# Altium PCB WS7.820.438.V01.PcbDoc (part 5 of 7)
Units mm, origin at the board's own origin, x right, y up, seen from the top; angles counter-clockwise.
Board outline 143.01 x 224 mm, 4 copper layers (Top Layer, G2, S3, Bottom Layer); 863 components, 638 nets, 2623 pads, 4664 vias.
Unrouted connection lines stored in the file: 16.
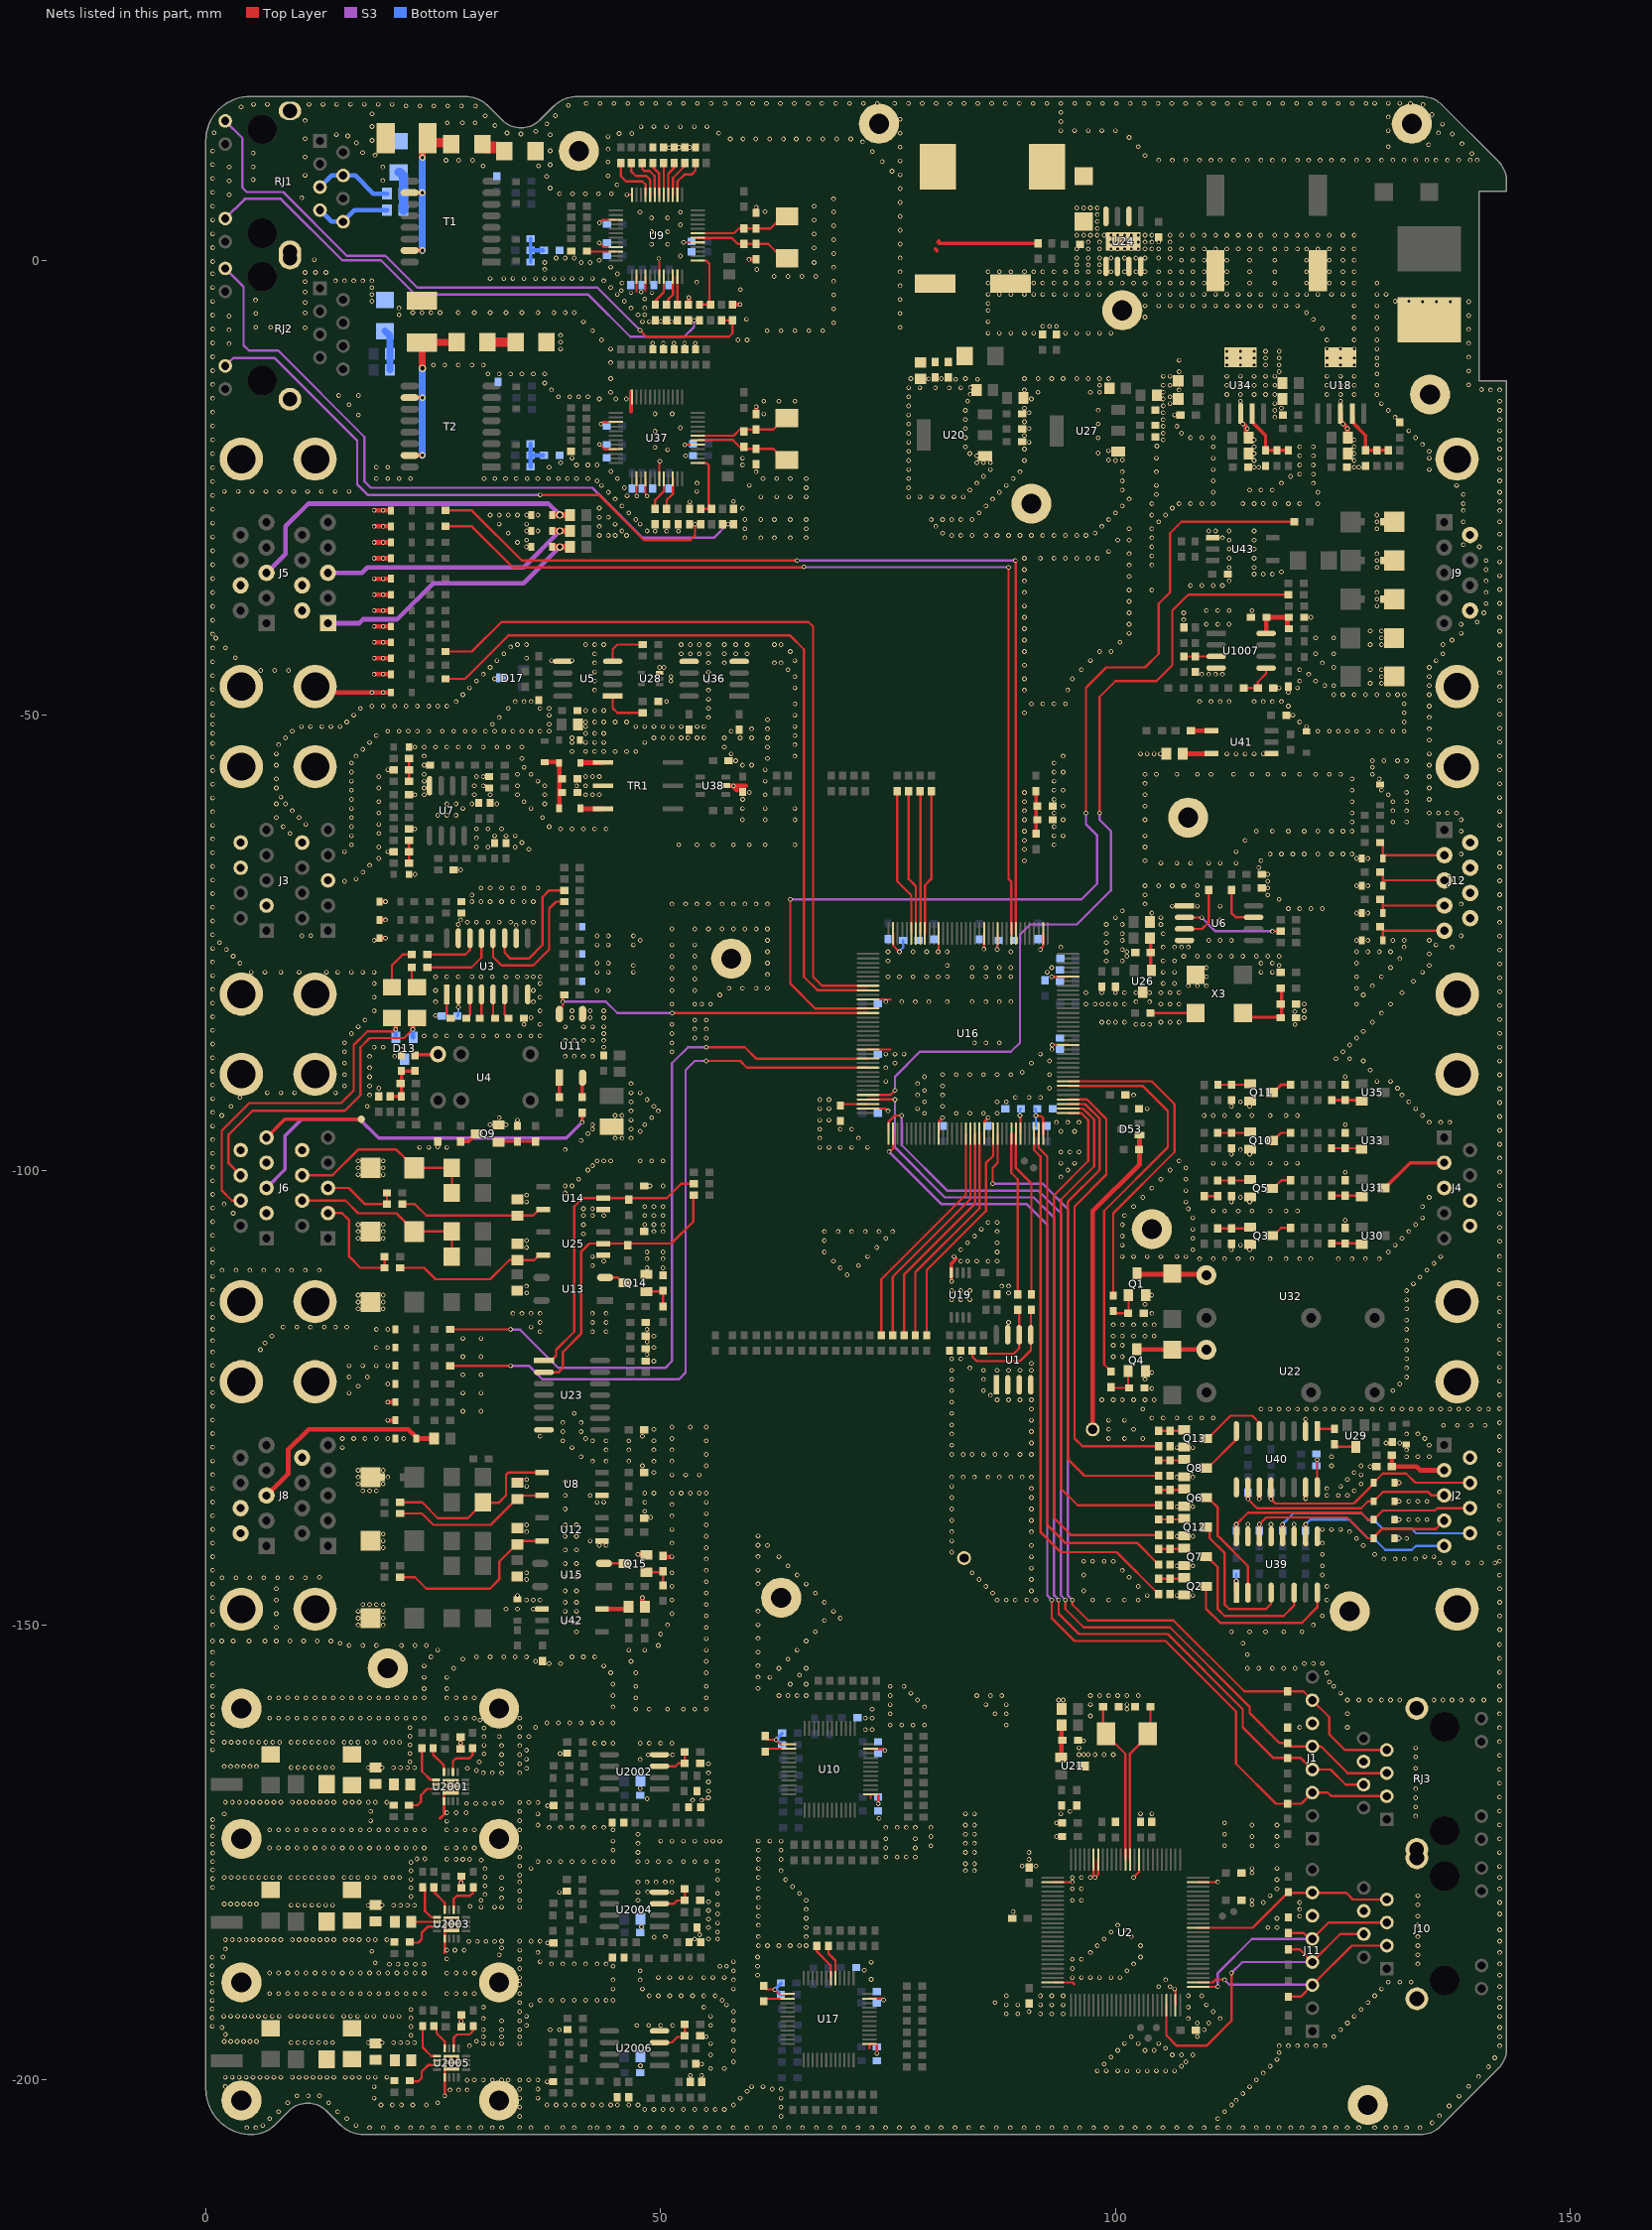
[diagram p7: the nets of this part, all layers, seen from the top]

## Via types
v1: diameter 0.508, hole 0.305, Top Layer to Bottom Layer, tented both sides, 4404 vias
v2: diameter 0.508, hole 0.3, Top Layer to Bottom Layer, tented both sides, 200 vias
v3: diameter 0.813, hole 0.508, Top Layer to Bottom Layer, tented both sides, 31 vias
v4: diameter 0.457, hole 0.305, Top Layer to Bottom Layer, tented both sides, 10 vias
v5: diameter 0.66, hole 0.406, Top Layer to Bottom Layer, tented both sides, 9 vias
v6: diameter 0.762, hole 0.406, Top Layer to Bottom Layer, tented both sides, 6 vias
v7: diameter 0.711, hole 0.406, Top Layer to Bottom Layer, tented both sides, 4 vias

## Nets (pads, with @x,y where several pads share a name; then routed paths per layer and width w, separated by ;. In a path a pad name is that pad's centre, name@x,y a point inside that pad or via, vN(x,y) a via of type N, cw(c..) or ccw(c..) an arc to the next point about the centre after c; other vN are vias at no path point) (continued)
GND: (continued)
  other v1: 128.5,17.25 130,17.25 131.25,17.25
  other v2: 0.75,-151.75 1.75,-151.75 3,-151.75 4.75,-151.75 6.5,-151.75 7.75,-151.75 9.25,-151.75 10.75,-151.75 12.25,-151.75 13.75,-151.75 55,-149 36,-148.25 55,-147.75 55,-146.5 86.5,-146.5 40.75,-146.25 55,-145.25 35.25,-145 40.75,-144.75 55,-144 90.75,-143.75 40.75,-143.25 55,-142.75 40.75,-141.75 55,-141.5 43.25,-141.25 42.25,-140.75 40.75,-140.25 55,-140.25 35.25,-139.75 35.25,-139 40.75,-139 55,-139 90.75,-138.5 55,-137.75 48.25,-137.5 82,-137.25 48.26,-136.525 43,-136.5 43.75,-136.5 55,-136.5 90.75,-136 42.25,-135.75 48.25,-135.5 55,-135.5 35.25,-134.75 82,-134.75 19.5,-134.5 35.25,-134 20,-133.75 87.25,-133.75 89.75,-133.75 48,-132.5 86.75,-131.25 89.5,-131.25 15,-130.5 49.25,-129.75 15,-129.5 16.25,-129.5 17.5,-129.5 18.75,-129.5 20,-129.5 48,-129.25 39.25,-128.75 49.25,-128.5 53.25,-128.25 82,-125.5 15.75,-124.5 16.75,-123.75 20,-123.5 82,-123 17.75,-122.75 15.75,-121.5 17.25,-121.5 18.75,-121.5 20,-121.5 48.5,-120.25 6,-119.75 20,-119.5 6.5,-119 48.514,-118.872 7.25,-118.25 20,-117.5 48.5,-117.5 8.5,-117.25 10,-117.25 11.5,-117.25 13,-117.25 14.25,-117.25 15.5,-117.25 35.25,-113.5 43.75,-110 42.5,-109.5 35.25,-107.75 48.25,-106 49.25,-106 43.75,-105 48.25,-105 49.25,-105 3,-104.75 42.5,-104.25 48.25,-104 49.25,-104 2,-103.75 35.25,-102.75 48.823,-101.75 43,-99 43.75,-99 44.5,-99 42,-96 42.5,-95 1.75,-94 2.75,-93 3.75,-92 41.5,-87.5 42.5,-87.5 43.75,-86.5 42.5,-85.75 43.75,-85 35.75,-83.25 42.25,-83.25 75,-76 77.75,-76 79.25,-76 10.55,-74.25 11.55,-74.217 59,-61.5 59.007,-59.25 59.757,-58.5 58.257,-55 19.5,-40.25 35.25,-30.75 35.25,-29.75 35.25,-29 35.25,-28 19.5,-27.5 43,-24.25 20,-22.75 37.25,-12.5 18.25,-4.5 18.25,-3.75 33.75,-2 35,-2 36.25,-2 37.25,-2 38.25,-2 45.25,-1.5 41.25,-0.25 42.25,-0.25 38.5,0.25
  other v4: 49.116,-9.111 50.29,-9.111 51.465,-9.111 52.64,-9.111 53.815,-9.111 51.228,-6.731 50.015,-6.706 46.736,-3.556 49.022,-3.556 49.809,0.178
GND2: C19.1 C20.1 C108.1 C110.1 C111.1 D17.3 D18.2 J3.B9 J3.B11 R33.2 R304.1 TR1.5 U5.5 U28.3 U36.5
  other v1: 15.25,-65 16,-64.25 16,-63.25 9.25,-63 8.5,-62.25 16,-62.25 11,-62 7.75,-61.25 10.25,-61.25 16,-61.25 9.5,-60.5 16,-60.25 7.75,-59.75 8.75,-59.75 16,-59.25 8.25,-59 16,-58.25 7.75,-58 16,-57.25 7.75,-57 16,-56.25 7.75,-55.5 16,-55.25 16.5,-54.5 7.75,-54.25 40.25,-54 41.75,-54 42.75,-54 43.75,-54 45,-54 46.25,-54 47.25,-54 17.25,-53.75 8,-53.25 18,-53 40.25,-53 41.75,-53 42.75,-53 43.75,-53 48.25,-53 8.75,-52.5 40.25,-52.5 49.25,-52.5 50.25,-52.5 51.25,-52.5 52.25,-52.5 53,-52.5 54,-52.5 54.75,-52.5 18.75,-52.25 41.75,-52 42.75,-52 43.75,-52 9.5,-51.75 20,-51.75 21.25,-51.75 22.25,-51.75 23.25,-51.75 24.5,-51.75 26,-51.75 27.25,-51.75 28.5,-51.75 29.5,-51.75 30.75,-51.75 31.75,-51.75 32.75,-51.75 33.75,-51.75 34.75,-51.75 35.75,-51.75 36.75,-51.75 37.75,-51.75 10.5,-51.25 11.5,-51.25 12.75,-51.25 13.75,-51.25 14.75,-51.25 41.75,-51.25 47.25,-51.25 48.25,-51.25 49.25,-51.25 50.25,-51.25 51.25,-51.25 52.25,-51.25 54,-51.25 54.75,-51.25 31.5,-51 37.75,-51 15.5,-50.75 41.75,-50.75 42.75,-50.75 43.75,-50.75 45,-50.75 46.25,-50.75 32.25,-50.25 55.25,-50.25 16.25,-50 37.75,-50 41.75,-49.5 42.75,-49.5 43.75,-49.5 17,-49.25 33.25,-49.25 36.75,-49.25 37.75,-49.25 55.25,-49.25 18.25,-49 19.5,-49 20.75,-49 22,-49 23.25,-49 24.5,-49 25.5,-49 26.5,-49 27.5,-48.5 34,-48.5 35,-48.5 35.75,-48.5 55.25,-48.25 28.25,-47.75 42.75,-47.25 55.25,-47.25 29,-47 29.75,-46.25 42.75,-46.25 55.25,-46.25 31.75,-46 30.5,-45.5 42.75,-45.25 55.25,-45.25 31.25,-44.75 42.75,-44.25 55.25,-44.25 32,-44 38,-44 40.25,-44 35.25,-43.75 32.75,-43.25 42.75,-43.25 52.25,-43.25 55.25,-43.25 33.5,-42.5 34.25,-42.25 35.25,-42.25 41.75,-42.25 42.75,-42.25 43.75,-42.25 52.25,-42.25 53.25,-42.25 54.25,-42.25 55.25,-42.25
  other v2: 41.757,-58.75 42.507,-58.75 43.257,-58.75 40.757,-57.75 41.757,-57.75 41.757,-56.75 42.507,-56.75 43.257,-56.75 50.632,-48.5 51.132,-46.25 51.132,-45.75 49.882,-44.75 50.382,-44.75 53.25,-43.25 54.25,-43.25
green_24V: J4.2 U31.3 | length 7.8
  Top Layer w0.381: U31.3@129.47,-101.96 129.62,-101.96 132.387,-99.193 J4.2@136.139,-99.193
green_ctrl: R106.2 R261.1 | length 1.5
  Top Layer w0.254: R106.2@109.75,-102.85 R261.1@111.25,-102.85
I_SENSOR1: D71.1 J12.5 R107.2 | length 8.4
  Top Layer w0.254: R107.2@129.1,-73.25 129.127,-73.25 129.4,-73.523 129.4,-73.697 ; D71.1@129.4,-74.75 129.4,-73.697 ; J12.5@136.16,-73.697 129.4,-73.697
I_SENSOR2: D72.1 J12.4 R174.2 | length 8.4
  Top Layer w0.254: R174.2@129.1,-70.25 129.127,-70.25 129.4,-70.523 129.4,-70.927 ; D72.1@129.4,-71.75 129.4,-70.927 ; J12.4@136.16,-70.927 129.4,-70.927
I_SENSOR3: D73.1 J12.3 R175.2 | length 8.4
  Top Layer w0.254: R175.2@129.1,-67.25 129.127,-67.25 129.4,-67.523 129.4,-68.157 ; D73.1@129.4,-68.75 129.4,-68.157 ; J12.3@136.16,-68.157 129.4,-68.157
IO_reset: R38.2 R152.2 U40.16 | length 3.7
  Top Layer w0.254: U40.16@122.174,-134.874 v1(122.174,-131.826)
  Bottom Layer w0.254: R38.2@122.174,-132.5 v1(122.174,-131.826)
IO_SHIDU: FB7.1 J6.A3 | length 42.6
  Top Layer w0.381: v1(41.362,-94.75) FB7.1@41.362,-93.687
  S3 w0.381: J6.A3@6.666,-101.963 8.706,-99.923 8.706,-96.235 10.529,-94.412 16.912,-94.412 19,-96.5 39.612,-96.5 v1(41.362,-94.75)
IOC_SHIDU: R18.2 U11.6 U16.86 | length 36.4
  Top Layer w0.254: U11.6@38.875,-82.852 38.875,-82.305 39.25,-81.93 v1(39.25,-81.5) 39.25,-80.9 R18.2@39.4,-80.75 ; v1@51.25,-82.75 v1(51.263,-82.737) U16.86@72.801,-82.737
  S3 w0.254: v1(39.25,-81.5) 44,-81.5 45.237,-82.737 v1(51.263,-82.737)
JTCK: J1.5 R8.2 RJ3.5 U16.109 | length 113.8
  Top Layer w0.254: U16.109@75.051,-95.987 75.051,-94.699 75.75,-94 v1(76.5,-94) ; v1(94.498,-147.252) 94.5,-147.254 94.5,-148.25 96.5,-150.25 106,-150.25 114.75,-159 114.75,-159.674 118.059,-162.982 R8.2@118.923,-162.982 118.923,-163.032 119.196,-163.305 119.305,-163.305 119.345,-163.345 J1.5@121.641,-163.345 122.595,-163.345 125.528,-166.278 RJ3.5@129.824,-166.278
  S3 w0.254: v1(76.5,-94) 76.5,-97.25 81.5,-102.25 91.5,-102.25 94,-104.75 94,-146.75 94.498,-147.248 v1(94.498,-147.252)
JTCK-1: J10.5 J11.5 R157.2 U2.76 | length 27.5
  Top Layer w0.254: U2.76@109.096,-189.781 109.112,-189.766 111.234,-189.766 v1(111.25,-189.75) ; R157.2@119,-183.85 120.691,-183.85 121.341,-184.5 J11.5@121.641,-184.5 123.436,-182.705 J10.5@129.84,-182.705
  S3 w0.254: v1(111.25,-189.75) 111.25,-188.25 115,-184.5 J11.5@121.641,-184.5
JTDI: J1.3 R5.1 RJ3.3 U16.110 | length 115.7
  Top Layer w0.254: v1(75.115,-97.967) 75.163,-97.918 75.251,-97.918 75.551,-97.618 U16.110@75.551,-95.987 ; v1(92.998,-147.252) 93,-147.254 93,-149.25 95.5,-151.75 105.5,-151.75 113.25,-159.5 113.25,-165.25 117.65,-169.65 R5.1@118.923,-169.65 120.415,-169.65 J1.3@121.641,-168.425 ; J1.3@121.641,-168.425 123.355,-168.425 123.748,-168.818 RJ3.3@129.824,-168.818
  S3 w0.254: v1(75.115,-97.967) 80.898,-103.75 90.25,-103.75 92.5,-106 92.5,-146.75 92.998,-147.248 v1(92.998,-147.252)
JTDI-1: J10.3 J11.3 R148.1 U2.77 | length 26.1
  Top Layer w0.254: U2.77@109.096,-189.281 110.719,-189.281 111.049,-188.951 111.951,-188.951 v1(112,-189) ; R148.1@119,-190.85 120.371,-190.85 J11.3@121.641,-189.58 125.976,-185.245 J10.3@129.84,-185.245
  S3 w0.254: v1(112,-189) 112.54,-189.54 121.601,-189.54 J11.3@121.641,-189.58
JTDO: J1.7 R7.1 RJ3.7 U16.133 | length 101.1
  Top Layer w0.254: v1(86.5,-101.5) 86.5,-99.75 87.051,-99.199 U16.133@87.051,-95.987 ; v1(95.248,-147.252) 95.25,-147.254 95.25,-147.75 97,-149.5 106.371,-149.5 114.173,-157.302 R7.1@118.923,-157.302 120.677,-157.302 J1.7@121.641,-158.265 123.5,-160.125 123.5,-162 125.238,-163.738 RJ3.7@129.824,-163.738
  S3 w0.254: v1(86.5,-101.5) 92,-101.5 94.75,-104.25 94.75,-146.75 95.248,-147.248 v1(95.248,-147.252)
JTDO-1: J10.7 J11.7 R156.1 U2.89 | length 22.7
  Top Layer w0.254: U2.89@109.096,-183.281 115.069,-183.281 118.677,-179.673 118.727,-179.673 119,-179.4 R156.1@119,-179.35 ; R156.1@119,-179.42 J11.7@121.641,-179.42 125.368,-179.42 126.113,-180.165 J10.7@129.84,-180.165
JTMS: J1.4 R6.1 RJ3.4 U16.105 | length 115.1
  Top Layer w0.254: U16.105@72.801,-92.237 72.807,-92.244 75.744,-92.244 v1(75.75,-92.25) ; v1(93.748,-147.252) 93.75,-147.254 93.75,-148.75 96,-151 105.75,-151 114,-159.25 114,-161.25 117.366,-164.616 R6.1@118.923,-164.616 120.371,-164.616 J1.4@121.641,-165.885 123.635,-165.885 125.298,-167.548 RJ3.4@127.284,-167.548
  S3 w0.254: v1(75.75,-92.25) 75.75,-97.5 81.25,-103 91,-103 93.25,-105.25 93.25,-146.75 93.748,-147.248 v1(93.748,-147.252)
JTMS-1: J10.4 J11.4 R155.1 U2.72 | length 36.9
  Top Layer w0.254: U2.72@105.596,-191.781 105.596,-195.096 106.75,-196.25 110,-196.25 112.75,-193.5 v1(112.75,-188.25) ; R155.1@119,-185.65 120.251,-185.65 J11.4@121.641,-187.04 124.706,-183.975 J10.4@127.3,-183.975
  S3 w0.254: v1(112.75,-188.25) 113.96,-187.04 J11.4@121.641,-187.04
LCD_RX: D13.2 F1.2 J6.A8 | length 35.4
  Top Layer w0.254: J6.A8@3.813,-100.565 2.5,-99.252 2.5,-96.103 5.131,-93.472 15.278,-93.472 17,-91.75 17,-86.5 18,-85.5 21.785,-85.5 v1(22.753,-84.531)
  Top Layer w0.508: v1(22.753,-84.531) 22.753,-83.722 F1.2@23.15,-83.325
  Bottom Layer w0.508: v1(22.753,-84.531) 22.753,-85.373 D13.2@22.794,-85.414
LCD_TX: D13.1 F2.2 J6.A7 | length 38
  Top Layer w0.254: J6.A7@3.826,-103.348 2.859,-103.348 1.75,-102.239 1.75,-95.659 4.775,-92.634 14.866,-92.634 16.25,-91.25 16.25,-86.25 17.75,-84.75 20.578,-84.75 20.796,-84.531 v1(20.853,-84.531)
  Top Layer w0.508: F2.2@20.483,-83.325 20.853,-83.696 v1(20.853,-84.531)
  Bottom Layer w0.508: v1(20.853,-84.531) 20.853,-85.373 D13.1@20.894,-85.414
LINKLED: R78.2 R165.1 U9.25 | length 7.7
  Top Layer w0.254: U9.25@54.092,-0.037 55.003,-0.037 55.365,-0.399 55.365,-3.059 55.365,-3.556 ; R78.2@54.349,-4.756 54.248,-4.858 R165.1@55.442,-4.858 ; 55.365,-3.879 55.365,-3.556 ; R165.1@55.479,-4.895 R165.1@55.442,-4.858 ; 55.365,-3.556 55.365,-4.756 55.467,-4.858 R165.1@55.442,-4.858
LINKLED2: R162.2 R280.2 U37.25 | length 7.2
  Top Layer w0.254: U37.25@54.092,-22.275 55.042,-22.275 55.267,-22.501 R162.2@55.267,-27.311 ; R280.2@54.581,-27.311 R162.2@55.695,-27.311
M_SCL: R2.1 R12.2 U1.6 | length 8.4
  Top Layer w0.254: R2.1@85.5,-119.85 85.5,-119.9 85.773,-120.173 88.827,-120.173 89.425,-119.575 R12.2@89.425,-115.525
M_SDA: R3.1 R11.2 U1.5 | length 12.5
  Top Layer w0.254: R3.1@84.25,-119.85 84.282,-119.882 84.282,-120.532 84.75,-121 89.5,-121 90.695,-119.805 R11.2@90.695,-115.1
Machine_LED1: D28.1 J2.5 R337.2 U39.10 | length 18.2
  Top Layer w0.508: v1(120.904,-138.938) 120.904,-140.253 U39.10@120.915,-140.264
  Bottom Layer w0.254: v1(120.904,-138.938) 121.412,-138.43 125.73,-138.43 127.762,-140.462 D28.1@128.27,-140.462 ; D28.1@128.39,-140.462 128.39,-140.562 128.588,-140.76 128.688,-140.76 129.678,-141.75 132.57,-141.75 133.017,-141.303 J2.5@136.065,-141.303
Machine_LED1_CPU: R39.1 U16.141 | length 59.9
  Top Layer w0.254: U16.141@91.051,-95.987 91.051,-97.801 91.75,-98.5 91.75,-139.75 93.986,-141.986 100.136,-141.986 R39.1@104.75,-146.6
Machine_LED1_OC: Q2.3 U39.8 | length 17.7
  Top Layer w0.254: Q2.3@109.95,-145.75 109.95,-148.2 111.5,-149.75 120.5,-149.75 122.185,-148.065 U39.8@122.185,-146.436
Machine_LED2: D29.1 J2.9 R333.2 U39.12 | length 23.4
  Top Layer w0.508: v1(118.364,-138.938) 118.364,-140.253 U39.12@118.375,-140.264
  Bottom Layer w0.254: v1(118.364,-138.938) 119.634,-137.668 127,-137.668 127.762,-138.43 D29.1@128.39,-138.43 128.39,-138.53 128.588,-138.728 128.688,-138.728 129.406,-139.446 132.588,-139.446 133.06,-139.918 138.902,-139.918 J2.9@138.938,-139.954
Machine_LED2_CPU: R340.1 U16.142 | length 57.5
  Top Layer w0.254: U16.142@91.551,-95.987 91.551,-97.551 92.5,-98.5 92.5,-139 94.47,-140.97 102.37,-140.97 R340.1@104.75,-143.35
Machine_LED2_OC: Q7.3 U39.6 | length 16.5
  Top Layer w0.254: Q7.3@110.346,-142.746 111.252,-143.652 111.252,-148.252 112,-149 118.5,-149 119.622,-147.878 119.622,-146.459 U39.6@119.645,-146.436
Machine_LED3: D30.1 J2.4 R331.2 U39.14 | length 23.6
  Top Layer w0.254: v1(115.824,-138.938) 116.586,-138.176 125.476,-138.176 127.762,-140.462 D30.1@128.39,-140.462 ; D30.1@128.39,-140.362 129.306,-139.446 135.225,-139.446 135.987,-138.684 J2.4@136.144,-138.684
  Top Layer w0.508: v1(115.824,-138.938) 115.824,-140.253 U39.14@115.835,-140.264
Machine_LED3_CPU: R344.1 U16.1 | length 60.1
  Top Layer w0.254: U16.1@94.801,-93.737 96.237,-93.737 97,-94.5 97,-99 93.25,-102.75 93.25,-138.25 95.1,-140.1 R344.1@104.75,-140.1
Machine_LED3_OC: Q12.3 U39.4 | length 16.2
  Top Layer w0.254: Q12.3@110.002,-139.496 Q12.3@110.152,-139.496 ; Q12.3@110.152,-139.246 110.363,-139.457 110.363,-140.462 112.014,-142.113 112.014,-147.764 112.5,-148.25 116.54,-148.25 117.102,-147.688 117.102,-146.439 U39.4@117.105,-146.436
Machine_LED4: D31.1 J2.8 R34.2 U39.16 | length 28.7
  Top Layer w0.254: v1(113.284,-138.938) 114.554,-137.668 127,-137.668 127.762,-138.43 D31.1@128.39,-138.43 128.39,-138.33 128.588,-138.132 128.688,-138.132 129.406,-137.414 135.128,-137.414 135.382,-137.16 J2.8@139.192,-137.16
  Top Layer w0.508: v1(113.284,-138.938) 113.284,-140.253 U39.16@113.295,-140.264
Machine_LED4_CPU: R40.1 U16.2 | length 56.9
  Top Layer w0.254: U16.2@94.801,-93.237 96.444,-93.237 97.656,-94.449 97.656,-99.594 94,-103.25 94,-135 95.85,-136.85 R40.1@104.75,-136.85
Machine_LED4_OC: Q6.3 U39.2 | length 12.4
  Top Layer w0.254: Q6.3@110.002,-136 110.152,-136 110.525,-136.373 111.252,-137.1 111.252,-140.208 114.565,-143.521 U39.2@114.565,-146.436
Machine_LED5: D32.1 J2.3 R339.2 U40.10 | length 24.1
  Top Layer w0.254: v1(114.554,-136.144) 115.57,-137.16 127,-137.16 127.762,-136.398 D32.1@128.27,-136.398 ; D32.1@128.39,-136.398 128.39,-136.298 128.588,-136.1 128.688,-136.1 129.406,-135.382 134.382,-135.382 134.763,-135.763 J2.3@136.139,-135.763
  Top Layer w0.508: v1(114.554,-136.144) U40.10@114.554,-134.874
Machine_LED5_CPU: R341.1 U16.3 | length 53.7
  Top Layer w0.254: U16.3@94.801,-92.737 96.652,-92.737 98.25,-94.336 98.25,-100 94.75,-103.5 94.75,-131.75 96.6,-133.6 R341.1@104.75,-133.6
Machine_LED5_OC: Q8.3 U40.8 | length 5.5
  Top Layer w0.254: Q8.3@110.002,-132.75 110.152,-132.75 113.218,-129.684 113.218,-128.768 U40.8@113.284,-128.702
Machine_LED6: D33.1 J2.7 R335.2 U40.12 | length 25.2
  Top Layer w0.254: v1(117.094,-136.144) 117.602,-136.652 126.204,-136.652 128.27,-134.586 D33.1@128.27,-134.366 ; D33.1@128.39,-134.366 128.39,-134.266 128.588,-134.068 128.688,-134.068 129.406,-133.35 131.953,-133.35 132.969,-134.366 J2.7@138.938,-134.366
  Top Layer w0.508: v1(117.094,-136.144) U40.12@117.094,-134.874
Machine_LED6_CPU: R345.1 U16.4 | length 51.3
  Top Layer w0.254: U16.4@94.801,-92.237 96.859,-92.237 99,-94.379 99,-100.5 95.5,-104 95.5,-129.49 96.36,-130.35 R345.1@104.75,-130.35
Machine_LED6_OC: Q13.3 U40.6 | length 8.2
  Top Layer w0.254: Q13.3@110.002,-129.5 110.152,-129.5 112.652,-127 115.04,-127 115.819,-127.779 U40.6@115.819,-128.848
MAGNETIC_SW1: R196.1 U16.7 | length 44
  Top Layer w0.254: U16.7@94.801,-90.737 102.987,-90.737 105.75,-93.5 105.75,-97.5 98.75,-104.5 98.75,-121.35 99.5,-122.1 R196.1@99.5,-122.15
MAGNETIC_SW2: R28.1 U16.8 | length 36.6
  Top Layer w0.254: U16.8@94.801,-90.237 103.987,-90.237 106.5,-92.75 106.5,-98 99.75,-104.75 R28.1@99.75,-113.8
MPS1: R219.2 R311.2 U14.5 U23.1 | length 33
  Top Layer w0.254: U23.1@37.164,-120.94 37.964,-120.94 38.5,-120.404 38.5,-119.75 40.5,-117.75 40.5,-104 41.425,-103.075 U14.5@43.7,-103.075 46.5,-103.075 50.675,-103.075 52.25,-101.5 R311.2@53.65,-101.5
MPS1+: D49.2 J6.B8 R191.1 R194.2 | length 21.3
  Top Layer w0.254: J6.B8@10.586,-100.578 13.922,-100.578 16.75,-97.75 20.95,-97.75 21.927,-98.727 22.75,-99.55 D49.2@22.75,-99.75 ; D49.2@22.9,-100 D49.2@22.9,-99.95 ; D49.2@22.9,-99.75 R191.1@27,-99.75 ; R191.1@27.05,-99.75 27.05,-102.3 R194.2@27.25,-102.5
MPS1-: J6.B3 R198.2 R199.2 | length 8.2
  Top Layer w0.254: J6.B3@13.426,-101.963 15.713,-101.963 17.5,-103.75 R199.2@19.9,-103.75 R198.2@19.9,-102.75
MPS2: R220.2 R310.2 U23.2 U25.5 | length 32.5
  Top Layer w0.254: U23.2@37.164,-122.21 38.79,-122.21 39.25,-121.75 39.25,-120 41.25,-118 41.25,-109 42.175,-108.075 U25.5@43.7,-108.075 46.4,-108.075 51.175,-108.075 53.6,-105.65 53.6,-102.8 R310.2@53.65,-102.75
MPS2+: D51.2 J6.B7 R201.1 R204.2 | length 20.6
  Top Layer w0.254: J6.B7@10.586,-103.348 15.348,-103.348 16.75,-104.75 20.95,-104.75 22.75,-106.55 D51.2@22.75,-106.75 ; D51.2@22.9,-106.75 R201.1@27,-106.75 ; R204.2@27,-109.5 27.05,-109.45 R201.1@27.05,-106.75
MPS2-: J6.B2 R206.2 R207.2 | length 12.3
  Top Layer w0.254: J6.B2@13.426,-104.733 14.983,-104.733 15.75,-105.5 15.75,-109.5 17,-110.75 R207.2@19.65,-110.75 R206.2@19.65,-109.5
NetBT1_1: BT1.1 D53.1 R216.1 | length 34.5
  Top Layer w0.508: BT1.1@97.5,-128.5 97.5,-104.5 102.65,-99.35 D53.1@102.65,-96.15
NetC10_1: C10.1 FB5.1 U16.143 | length 4.6
  Top Layer w0.254: v1(91.25,-94) 91.299,-94.049 91.799,-94.049 92.051,-94.301 U16.143@92.051,-95.987
  Bottom Layer w0.254: C10.1@91.15,-93.25 91.25,-93.35 FB5.1@91.25,-95.15
NetC12_1: C12.1 U3.4 | length 5.2
  Top Layer w0.254: C12.1@30.1,-83.303 30.302,-83.101 U3.4@30.302,-80.683 ; 30.302,-82.821 U3.4@30.302,-80.683 ; U3.4@30.302,-80.302 U3.4@30.302,-80.683
NetC12_2: C12.2 U3.5 | length 5.2
  Top Layer w0.254: 31.572,-82.796 U3.5@31.572,-80.683 ; U3.5@31.572,-80.302 U3.5@31.572,-80.683 ; C12.2@31.8,-83.303 31.572,-83.076 U3.5@31.572,-80.683
NetC15_1: C15.1 U3.6 | length 5.1
  Top Layer w0.254: 32.842,-82.591 U3.6@32.842,-80.683 ; U3.6@32.842,-80.302 U3.6@32.842,-80.683 ; C15.1@33.275,-83.303 32.842,-82.871 U3.6@32.842,-80.683
NetC16_1: C16.1 U3.1 | length 4
  Top Layer w0.254: 26.492,-82.591 26.492,-81.813 ; U3.1@26.492,-80.302 U3.1@26.492,-80.683 26.492,-81.813 ; C16.1@26.925,-83.303 26.492,-82.871 26.492,-81.813
NetC16_2: C16.2 U3.3 | length 5.1
  Top Layer w0.254: C16.2@28.625,-83.303 29.032,-82.896 U3.3@29.032,-80.683 ; 29.032,-82.616 U3.3@29.032,-80.683 ; U3.3@29.032,-80.302 U3.3@29.032,-80.683
NetC17_1: C17.1 U3.2 | length 2.4
  Top Layer w0.254: v1(27.762,-82.093) U3.2@27.762,-80.683
  Bottom Layer w0.254: C17.1@27.647,-83.058 27.762,-82.943 v1(27.762,-82.093)
NetC23_2: C23.2 U16.106 | length 3.1
  Top Layer w0.254: C23.2@69.75,-92.9 69.913,-92.737 U16.106@72.801,-92.737
NetC24_1: C24.1 U16.71 | length 3.8
  Top Layer w0.254: U16.71@75.551,-73.987 75.568,-74.004 75.568,-75.318 v1(76.25,-76)
  Bottom Layer w0.254: v1@76.201,-76.049 v1(76.25,-76) 76.25,-75.931 76.65,-75.531 C24.1@76.65,-74.75
NetC40_2: C40.2 R61.1 R63.1 R65.1 | length 3.9
  Bottom Layer w0.381: R65.1@35.704,-0.197 R63.1@35.704,2.381
  Bottom Layer w0.508: R61.1@35.704,1.073 C40.2@37.052,1.073
NetC42_2: C42.2 R75.2 U9.30 X2.2 | length 10.2
  Top Layer w0.254: U9.30@54.092,2.463 57.811,2.463 58.477,1.797 C42.2@60.496,1.797 61.816,1.797 X2.2@63.392,0.222
NetC43_2: C43.2 R73.1 RJ1.9 | length 71.6
  Top Layer w0.254: v2(47.725,-7.7) 48.432,-8.407 57.506,-8.407 57.905,-8.008 57.905,-7.13 C43.2@57.905,-6.595 R73.1@56.692,-6.595
  S3 w0.254: RJ1.9@2.14,15.312 4.001,13.452 4.001,7.999 4.5,7.5 8.5,7.5 15.5,0.5 19.75,0.5 23.25,-3 43.025,-3 v2(47.725,-7.7)
NetC44_2: C44.2 R75.1 U9.31 X2.1 | length 10.1
  Top Layer w0.254: U9.31@54.092,2.963 58.067,2.963 58.605,3.501 C44.2@60.496,3.501 62.07,3.501 X2.1@63.392,4.822
NetC45_2: C45.2 U9.20 | length 3.6
  Top Layer w0.254: C45.2@49.361,-4.842 C45.2@49.414,-4.788 ; C45.2@49.414,-4.895 C45.2@49.414,-4.788 ; U9.20@50.342,-1.787 50.342,-3.506 49.414,-4.434 C45.2@49.414,-4.788
NetC46_2: C46.2 R78.1 RJ1.11 | length 61
  Top Layer w0.254: C46.2@53.105,-6.595 v2(53.676,-6.595) R78.1@54.248,-6.595
  S3 w0.254: RJ1.11@2.14,4.592 4.298,6.75 8.25,6.75 15,0 19.25,0 23,-3.75 42,-3.75 46.657,-8.407 52.593,-8.407 53.676,-7.324 v2(53.676,-6.595)
NetC47_1: C47.1 U9.22 | length 3.4
  Top Layer w0.254: C47.1@50.627,-4.895 50.775,-4.748 50.775,-4.343 51.342,-3.776 U9.22@51.342,-1.787
NetC48_2: C48.2 R74.1 R76.1 | length 4.4
  Bottom Layer w1.016: C48.2@21.209,9.675 21.309,9.675 21.728,9.256 R76.1@21.728,5.506
NetC49_2: C49.2 R79.1 | length 1.7
  Top Layer w1.27: R79.1@30.39,12.769 30.746,12.412 31.915,12.412
NetC52_1: C52.1 C53.1 FB14.1 U17.1 | length 4.8
  Top Layer w0.229: FB14.1@61.342,-189.792 61.614,-190.064 v1(62.545,-190.064) 63.04,-190.559 U17.1@63.954,-190.559
  Bottom Layer w0.381: C53.1@63.222,-190.606 62.68,-190.064 v1(62.545,-190.064) 63.222,-189.387 C52.1@63.222,-189.336
NetC57_1: C57.1 C82.1 C83.1 C164.1 FB12.1 L11.2 R102.2 | length 11.3
  Top Layer w0.381: 80.178,1.27 80.393,1.055 ; 80.5,2 80.6,2.1 ; 80.6,1.85 R102.2@91.5,1.85
NetC61_1: C61.1 U2.12 X1.2 | length 17.8
  Top Layer w0.254: U2.12@101.596,-175.781 101.596,-164.154 X1.2@103.75,-162 ; X1.2@103.55,-161.976 103.85,-161.676 C61.1@103.85,-159
NetC62_1: C62.1 U2.13 X1.1 | length 17.8
  Top Layer w0.254: C62.1@98.65,-159 98.65,-161.676 X1.1@98.95,-161.976 ; X1.1@98.9,-161.976 101.096,-164.172 U2.13@101.096,-175.781
NetC63_1: C63.1 C64.1 FB27.1 U10.1 | length 4.8
  Top Layer w0.229: FB27.1@61.482,-162.342 61.754,-162.614 v1(62.685,-162.614) 63.18,-163.109 U10.1@64.094,-163.109
  Bottom Layer w0.381: C64.1@63.362,-163.156 62.82,-162.614 v1(62.685,-162.614) C63.1@63.362,-161.937
NetC84_2: C84.2 FB34.2 R149.1 | length 2.5
  Top Layer w0.254: R149.1@22.35,-57.25 C84.2@22.35,-56 FB34.2@22.35,-54.75
NetC94_1: C94.1 FB20.1 J2.2 | length 7.4
  Top Layer w0.508: C94.1@130.39,-132.588 133.096,-132.588 133.501,-132.993 J2.2@136.139,-132.993 ; FB20.1@130.39,-131.318 130.39,-132.5 130.302,-132.588 C94.1@130.44,-132.588
NetC101_2: C101.2 L2.2 U21.1 | length 3.6
  Top Layer w0.508: U21.1@94.05,-164.55 94.075,-164.525 94.075,-161.025 L2.2@94.1,-161
NetC111_2: C111.2 D52.1 D62.2 D63.1 R304.2 | length 6.7
  Top Layer w0.508: D62.2@37.25,-55.15 38.786,-55.15 D63.1@38.857,-55.221 ; D52.1@38.857,-60.25 D63.1@38.857,-55.25 D63.1@38.857,-55.221 ; D63.1@38.857,-55.15 D63.1@38.857,-55.221
NetC118_2: C118.2 FB29.1 U30.2 | length 3.3
  Top Layer w0.254: FB29.1@123.77,-108.06 C118.2@125.27,-108.06 126.97,-108.06 U30.2@127.07,-108.16
NetC119_2: C119.2 FB30.1 U31.2 | length 3.3
  Top Layer w0.254: FB30.1@123.77,-102.81 C119.2@125.27,-102.81 126.97,-102.81 U31.2@127.07,-102.91
NetC120_2: C120.2 FB31.1 U33.2 | length 3.3
  Top Layer w0.254: FB31.1@123.75,-97.6 C120.2@125.25,-97.6 126.95,-97.6 U33.2@127.05,-97.7
NetC121_2: C121.2 FB32.1 U35.2 | length 3.3
  Top Layer w0.305: FB32.1@123.77,-92.31 C121.2@125.27,-92.31 126.97,-92.31 U35.2@127.07,-92.41
NetC123_2: C123.2 FB35.2 R306.1 | length 2.5
  Top Layer w0.254: FB35.2@22.35,-66.25 R306.1@22.35,-63.75
NetC131_1: C131.1 R108.1 R110.2 U18.4 | length 7.2
  Top Layer w0.381: U18.4@126.02,-16.85 126.105,-16.934 126.105,-17.854 127.5,-19.25 R110.2@127.5,-20.9 C131.1@128.75,-20.9 R108.1@130,-20.9
NetC138_2: C138.2 C139.1 FB4.1 X3.4 | length 7.6
  Top Layer w0.381: X3.4@114.003,-82.736 114.468,-83.201 C139.1@118.038,-83.201 ; C139.1@118.288,-83.451 118.288,-81.75 FB4.1@118.288,-80.064
NetC172_2: C172.2 R179.2 R180.2 R181.2 | length 4.6
  Top Layer w0.381: R180.2@91.288,-63.034 R179.2@91.288,-58.384
NetC173_2: C173.2 L12.2 U26.1 | length 3.5
  Top Layer w0.381: U26.1@103.886,-77.82 L12.2@103.886,-74.321
NetC207_1: C207.1 R159.1 R163.2 U34.4 | length 7.2
  Top Layer w0.381: U34.4@114.992,-16.848 115.076,-16.933 115.076,-17.826 116.5,-19.25 R163.2@116.5,-20.9 R159.1@117.75,-20.9 C207.1@119,-20.9
NetC234_2: C234.2 R263.1 R265.1 R267.1 | length 3.9
  Bottom Layer w0.508: R267.1@35.704,-22.695 R265.1@35.704,-20.175 ; R263.1@35.704,-21.445 C234.2@37.052,-21.445
NetC236_2: C236.2 R277.2 U37.30 X5.2 | length 10.7
  Top Layer w0.254: U37.30@54.092,-19.775 54.127,-19.741 57.937,-19.741 58.911,-20.715 C236.2@60.496,-20.715 62.391,-20.715 63.636,-21.96 X5.2@63.886,-21.96
NetC237_2: C237.2 R275.1 RJ2.9 | length 75.9
  Top Layer w0.254: R275.1@56.802,-29.011 v1(57.404,-29.011) C237.2@58.007,-29.011 C237.2@58,-29.018
  S3 w0.254: RJ2.9@2.14,-0.897 4.153,-2.91 4.153,-9.343 4.724,-9.915 7.933,-9.915 17.435,-19.416 17.435,-24.308 18.127,-25 42.5,-25 48,-30.5 55.863,-30.5 v1@57.352,-29.011
NetC238_2: C238.2 R277.1 U37.31 X5.1 | length 10.6
  Top Layer w0.254: U37.31@54.092,-19.275 58.042,-19.275 58.713,-18.605 C238.2@60.496,-18.605 62.391,-18.605 63.636,-17.36 X5.1@63.886,-17.36
NetC239_2: C239.2 U37.20 | length 4
  Top Layer w0.254: C239.2@49.383,-27.311 C239.2@49.403,-27.292 ; C239.2@49.656,-27.039 C239.2@49.403,-27.292 ; U37.20@50.342,-24.025 50.342,-25.401 49.403,-26.34 C239.2@49.403,-27.292
NetC240_2: C240.2 R280.1 RJ2.11 | length 65.9
  Top Layer w0.254: v1(36.75,-25.781) 43.206,-25.781 48.175,-30.75 53.25,-30.75 53.772,-30.228 v1(53.772,-29.011) ; C240.2@53.186,-29.011 v1(53.772,-29.011) ; R280.1@54.581,-29.011 R280.1@54.391,-29.011 v1(53.772,-29.011)
  S3 w0.254: RJ2.11@2.14,-11.609 3.022,-10.727 7.527,-10.727 16.637,-19.837 16.637,-24.638 17.78,-25.781 v1(36.75,-25.781)
NetC241_1: C241.1 U37.22 | length 3.6
  Top Layer w0.254: C241.1@50.656,-27.305 C241.1@50.65,-27.311 50.673,-27.288 50.673,-26.34 51.342,-25.671 U37.22@51.342,-24.025
NetC242_2: C242.2 R276.1 R278.1 | length 4.5
  Bottom Layer w0.762: C242.2@19.696,-7.775 19.709,-7.775 20.228,-8.294 R278.1@20.228,-12.053
NetC243_2: C243.2 R281.1 | length 3.1
  Top Layer w1.016: R281.1@30.95,-9 C243.2@34.05,-9
NetC1053_2: C1053.2 C1054.1 FB1007.2 U1007.8 | length 6
  Top Layer w0.381: U1007.8@115.848,-41.006 U1007.8@116.564,-41.006
  Top Layer w0.508: U1007.8@116.564,-41.006 116.6,-40.969 C1053.2@116.6,-39.25 118.9,-39.25 FB1007.2@118.9,-40.5
NetC1061_2: C1061.2 R1026.1 U1007.3 | length 3.6
  Top Layer w0.254: R1026.1@107.515,-43.542 107.519,-43.546 U1007.3@111.064,-43.546
NetC1068_2: C1068.2 R1038.1 U1007.5 | length 4.1
  Top Layer w0.254: R1038.1@114.1,-47 C1068.2@115.65,-47 115.65,-46.35 116.564,-45.436 U1007.5@116.564,-44.816
NetC2003_1: C2003.1 U2001.14 | length 4.4
  Top Layer w0.254: U2001.14@27.169,-166.169 27.169,-164.98 27.504,-164.646 28.951,-164.646 29.307,-164.29 C2003.1@29.307,-163.54
NetC2004_1: C2004.1 U2001.16 | length 3.1
  Top Layer w0.254: C2004.1@24.989,-163.54 24.989,-164.239 26.169,-165.42 U2001.16@26.169,-166.169
NetC2007_2: C2007.2 U2001.1 | length 4.5
  Top Layer w0.254: C2007.2@23.744,-163.54 23.744,-166.068 24.696,-167.019 U2001.1@25.319,-167.019
NetC2008_1: C2008.1 R2004.1 R2010.2 R2011.2
NetC2008_2: C2008.2 U2001.2 | length 0
  Top Layer w0.254: C2008.2@22.485,-167.516 C2008.2@22.489,-167.519
NetC2009_2: C2009.2 R2003.2 U2002.3 | length 4.2
  Top Layer w0.254: U2002.3@49.867,-165.519 51.625,-165.519 51.947,-165.196 C2009.2@52.646,-165.196 ; C2009.2@52.638,-165.188 C2009.2@52.646,-165.196 ; R2003.2@52.646,-163.952 C2009.2@52.646,-165.196
NetC2010_2: C2010.2 U2001.3 | length 4.1
  Top Layer w0.254: C2010.2@22.334,-169.802 23.262,-169.802 23.643,-169.421 23.643,-168.71 24.333,-168.019 U2001.3@25.319,-168.019
NetC2017_1: C2017.1 U2003.14 | length 4.2
  Top Layer w0.254: U2003.14@27.257,-181.284 27.257,-180.095 27.591,-179.761 29.039,-179.761 29.395,-179.405 C2017.1@29.395,-178.832
NetC2018_1: C2018.1 U2003.16 | length 2.9
  Top Layer w0.254: C2018.1@25.077,-178.832 25.077,-179.354 26.257,-180.535 U2003.16@26.257,-181.284
NetC2021_2: C2021.2 U2003.1 | length 4.2
  Top Layer w0.254: C2021.2@24.086,-178.871 24.086,-181.437 24.783,-182.134 U2003.1@25.407,-182.134
NetC2022_1: C2022.1 R2025.1 R2032.2 R2033.2
NetC2022_2: C2022.2 U2003.2 | length 2.8
  Top Layer w0.254: C2022.2@22.573,-182.631 22.576,-182.634 U2003.2@25.407,-182.634
NetC2025_2: C2025.2 R2026.2 U2004.3 | length 4.4
  Top Layer w0.254: U2004.3@49.867,-180.629 51.447,-180.629 51.795,-180.281 C2025.2@52.621,-180.281 ; C2025.2@52.553,-180.35 C2025.2@52.621,-180.281 ; R2026.2@52.646,-178.986 C2025.2@52.646,-180.256 ; C2025.2@52.702,-180.201 C2025.2@52.646,-180.256 ; C2025.2@52.621,-180.281 C2025.2@52.646,-180.256
NetC2026_2: C2026.2 U2003.3 | length 4.1
  Top Layer w0.254: C2026.2@22.421,-184.917 23.349,-184.917 23.73,-184.536 23.73,-183.825 24.421,-183.134 U2003.3@25.407,-183.134
NetC2031_1: C2031.1 U2005.14 | length 4.2
  Top Layer w0.254: U2005.14@27.257,-196.524 27.257,-195.335 27.591,-195.001 28.985,-195.001 29.395,-194.591 C2031.1@29.395,-194.072
NetC2032_1: C2032.1 U2005.16 | length 3
  Top Layer w0.254: C2032.1@25.356,-193.895 25.356,-194.874 26.257,-195.775 U2005.16@26.257,-196.524
NetC2035_2: C2035.2 U2005.1 | length 4.3
  Top Layer w0.254: C2035.2@23.832,-194.072 23.832,-196.423 24.783,-197.374 U2005.1@25.407,-197.374
NetC2036_1: C2036.1 R2043.1 R2050.2 R2051.2
NetC2036_2: C2036.2 U2005.2 | length 0
  Top Layer w0.254: C2036.2@22.573,-197.871 C2036.2@22.576,-197.874
NetC2039_2: C2039.2 R2045.2 U2006.3 | length 4.3
  Top Layer w0.254: U2006.3@49.867,-195.889 51.244,-195.889 51.845,-195.287 52.508,-195.287 C2039.2@52.644,-195.152 R2045.2@52.644,-193.907
NetC2040_2: C2040.2 U2005.3 | length 4.1
  Top Layer w0.254: C2040.2@22.421,-200.157 23.349,-200.157 23.73,-199.776 23.73,-199.065 24.421,-198.374 U2005.3@25.407,-198.374
NetD1_2: D1.2 L11.1 U24.2
NetD6_1: D6.1 FB8.1 J5.B1 | length 30.9
  Top Layer w0.635: D6.1@38.075,-31.5 v3(38.925,-31.5) FB8.1@40.025,-31.5
  S3 w0.508: J5.B1@13.426,-39.891 16.859,-39.891 17.29,-39.46 21.04,-39.46 25,-35.5 34.925,-35.5 v3(38.925,-31.5)
NetD11_1: D11.1 FB18.1 J5.A3 | length 39.6
  Top Layer w0.635: D11.1@38.075,-28 v3(38.925,-28) FB18.1@40.025,-28
  S3 w0.508: J5.A3@6.666,-34.351 8.75,-32.267 8.75,-29.25 11.25,-26.75 37.675,-26.75 v3(38.925,-28)
NetD12_1: D12.1 FB19.1 J5.B3 | length 29.4
  Top Layer w0.635: D12.1@38.075,-29.75 v3(38.925,-29.75) FB19.1@40.025,-29.75
  S3 w0.508: J5.B3@13.426,-34.351 17.149,-34.351 17.75,-33.75 34.925,-33.75 v3(38.925,-29.75)
NetD16_1: D16.1 FB36.1 J12.2 | length 8.8
  Top Layer w0.254: FB36.1@129.1,-64 129.127,-64 129.4,-64.273 D16.1@129.4,-65.65 ; D16.1@129.4,-65.75 D16.1@129.4,-65.65 ; J12.2@136.16,-65.387 129.663,-65.387 D16.1@129.4,-65.65
NetD41_1: D41.1 FB2.1 J8.A3 | length 23.3
  Top Layer w0.508: J8.A3@6.666,-135.769 9.05,-133.385 9.05,-130.75 11.3,-128.5 22.25,-128.5 23.079,-129.329 D41.1@23.15,-129.329 ; D41.1@23.15,-129.5 FB2.1@25.1,-129.5
NetD52_2: D52.2 TR1.6 | length 2.5
  Top Layer w0.508: D52.2@41.157,-60.25 41.193,-60.286 43.653,-60.286 TR1.6@43.657,-60.29
NetD60_1: D60.1 Q4.3 U22.4 | length 7.7
  Top Layer w0.508: Q4.3@102.35,-119.7 102.375,-119.725 109.975,-119.725 U22.4@110,-119.75
NetD61_1: D61.1 Q1.3 U32.4 | length 7.7
  Top Layer w0.508: Q1.3@102.37,-111.34 102.475,-111.445 U32.4@109.895,-111.445 ; U32.4@109.895,-111.195 U32.4@110,-111.3
NetD63_2: D63.2 TR1.4 | length 2.5
  Top Layer w0.508: D63.2@41.157,-55.25 41.193,-55.214 43.653,-55.214 TR1.4@43.657,-55.21
NetF1_1: F1.1 R52.2 | length 2.4
  Top Layer w0.254: R52.2@22.645,-77.724 22.645,-79.314 F1.1@23.216,-79.885
NetF2_1: F2.1 R49.2 | length 5.1
  Top Layer w0.254: F2.1@20.447,-79.885 20.447,-77.495 21.641,-76.302 R49.2@22.645,-76.302
NetFB3_1: FB3.1 R182.1 U8.3 | length 17.5
  Top Layer w0.254: R182.1@21.35,-137.75 23.75,-137.75 25,-139 31.3,-139 34.15,-136.15 FB3.1@34.25,-136.15 34.63,-135.77 U8.3@36.95,-135.77 36.98,-135.77 U8.3@37,-135.75
NetFB7_2: FB7.2 U11.3 | length 2.7
  Top Layer w0.381: FB7.2@41.362,-92.241 41.362,-89.651 U11.3@41.415,-89.598
NetFB10_1: FB10.1 U41.3 | length 3.2
  Top Layer w0.508: FB10.1@107.4,-54.25 107.41,-54.24 110.54,-54.24 U41.3@110.55,-54.23
NetFB11_1: FB11.1 R187.1 U12.3 | length 19.5
  Top Layer w0.254: R187.1@21.35,-144.75 23,-144.75 24.25,-146 31.25,-146 32.25,-145 32.25,-143.05 34.15,-141.15 FB11.1@34.25,-141.15 34.63,-140.77 U12.3@36.95,-140.77 36.98,-140.77 U12.3@37,-140.75
NetFB14_2: FB14.2 U17.2 | length 2.7
  Top Layer w0.229: FB14.2@61.342,-191.365 61.469,-191.365 61.775,-191.059 U17.2@63.954,-191.059
NetFB22_1: FB22.1 R199.1 U14.3 | length 16.3
  Top Layer w0.254: R199.1@21.6,-103.75 23,-103.75 24.25,-105 FB22.1@34.25,-105 35.995,-105 36.65,-104.345 U14.3@37.1,-104.345
NetFB24_1: FB24.1 R207.1 U25.3 | length 17.4
  Top Layer w0.254: R207.1@21.35,-110.75 24,-110.75 25.25,-112 31.25,-112 33.35,-109.9 36.095,-109.9 36.65,-109.345 U25.3@37.1,-109.345
NetFB27_2: FB27.2 U10.2 | length 2.7
  Top Layer w0.229: FB27.2@61.482,-163.915 61.609,-163.915 61.915,-163.609 U10.2@64.094,-163.609
NetFB33_1: FB33.1 U42.3 | length 2.7
  Top Layer w0.508: U42.3@43.55,-148.23 FB33.1@46.25,-148.23
NetFV1_2: FV1.2 R79.2 T1.10 T1.15 | length 17.5
  Top Layer w0.508: T1.15@22.404,1.073 v7(23.805,1.073) ; T1.10@22.404,7.423 v6(23.805,7.423)
  Top Layer w0.762: v7(23.805,11.295) FV1.2@23.805,12.92
  Top Layer w1.016: FV1.2@24.313,12.92 R79.2@27.141,12.92
  Bottom Layer w0.762: v7(23.805,1.073) v6(23.805,7.423) v7(23.805,11.295)
NetFV2_2: FV2.2 R281.2 T2.10 T2.15 | length 19
  Top Layer w0.508: T2.15@22.404,-21.445 v7@23.805,-21.445 ; T2.10@22.404,-15.095 v7@23.805,-15.095
  Top Layer w0.762: v3@23.805,-11.856 23.805,-9.105 FV2.2@23.75,-9.05 23.775,-9.025 27.525,-9.025 R281.2@27.55,-9
  Bottom Layer w0.762: v7@23.805,-21.445 v7(23.805,-21.42) v7(23.805,-15.121) v3(23.805,-11.87)
NetJ6_A5: J6.A5 TP2.1 | length 11.3
  Top Layer w0.381: J6.A5@6.666,-96.423 8.677,-94.412 TP2.1@17.094,-94.412
NetQ1_1: Q1.1 R28.2 R54.2 | length 3.5
  Top Layer w0.254: R28.2@99.75,-115.5 100,-115.75 R54.2@101.4,-115.75 ; Q1.1@101.42,-113.74 101.44,-113.76 R54.2@101.44,-115.5
NetQ2_1: Q2.1 R39.2 R315.2 | length 2.8
  Top Layer w0.254: R39.2@104.75,-144.9 107.45,-144.9 Q2.1@107.55,-144.8
NetQ3_1: Q3.1 R260.2 R262.1 | length 3.6
  Top Layer w0.254: R260.2@111.25,-106.4 R262.1@112.75,-106.4 114.68,-106.4 Q3.1@114.82,-106.26
NetQ3_3: Q3.3 R258.1 | length 2.1
  Top Layer w0.254: Q3.3@117.47,-107.11 118.22,-106.36 R258.1@119.27,-106.36
NetQ4_1: Q4.1 R195.2 R196.2 | length 3.9
  Top Layer w0.254: R196.2@99.5,-123.85 99.59,-123.94 R195.2@101.5,-123.94 101.4,-123.84 Q4.1@101.4,-122.1
NetQ5_1: Q5.1 R261.2 R291.1 | length 3.6
  Top Layer w0.254: R261.2@111.25,-101.15 R291.1@112.75,-101.15 114.7,-101.15 Q5.1@114.8,-101.05
NetQ5_3: Q5.3 R259.1 | length 2.4
  Top Layer w0.254: Q5.3@117.2,-102 117.35,-102 118.24,-101.11 R259.1@119.27,-101.11
NetQ6_1: Q6.1 R40.2 R316.2 | length 2.8
  Top Layer w0.254: R40.2@104.75,-135.15 107.45,-135.15 Q6.1@107.55,-135.05
NetQ7_1: Q7.1 R340.2 R342.2 | length 2.8
  Top Layer w0.254: R340.2@104.75,-141.65 R342.2@106,-141.65 107.45,-141.65 Q7.1@107.55,-141.55
NetQ8_1: Q8.1 R341.2 R343.2 | length 2.8
  Top Layer w0.254: R341.2@104.75,-131.9 R343.2@106,-131.9 107.45,-131.9 Q8.1@107.55,-131.8
NetQ9_1: Q9.1 R225.2 R226.2 | length 4.1
  Top Layer w0.254: Q9.1@32.25,-97 32.4,-96.85 R226.2@36.25,-96.85
NetQ9_3: Q9.3 R104.2 | length 2.2
  Top Layer w0.381: R104.2@28,-96.85 28.9,-96.85 29.34,-96.41 29.34,-96.31 29.65,-96 Q9.3@29.75,-96
NetQ10_1: Q10.1 R298.2 R300.1 | length 3.6
  Top Layer w0.254: R298.2@111.25,-95.9 R300.1@112.75,-95.9 114.7,-95.9 Q10.1@114.8,-95.8
NetQ10_3: Q10.3 R296.1 | length 2.4
  Top Layer w0.254: Q10.3@117.2,-96.75 117.35,-96.75 118.2,-95.9 R296.1@119.25,-95.9
NetQ11_1: Q11.1 R299.2 R301.1 | length 3.6
  Top Layer w0.254: R299.2@111.27,-90.61 R301.1@112.77,-90.61 114.72,-90.61 Q11.1@114.82,-90.51
NetQ11_3: Q11.3 R297.1 | length 2.4
  Top Layer w0.305: Q11.3@117.22,-91.46 117.37,-91.46 118.22,-90.61 R297.1@119.27,-90.61
NetQ12_1: Q12.1 R344.2 R346.2 | length 2.8
  Top Layer w0.254: R344.2@104.75,-138.4 R346.2@106,-138.4 107.45,-138.4 Q12.1@107.55,-138.3
NetQ13_1: Q13.1 R345.2 R347.2 | length 2.8
  Top Layer w0.254: R345.2@104.75,-128.65 R347.2@106,-128.65 107.35,-128.65 Q13.1@107.5,-128.5
NetQ14_1: Q14.1 R190.2 R348.2 | length 3.4
  Top Layer w0.254: Q14.1@48.444,-113.345 50.095,-113.345 R348.2@50.125,-113.375 ; R190.2@50.25,-115 R348.2@50.25,-113.25
NetQ14_3: Q14.3 U13.3 | length 2.3
  Top Layer w0.254: U13.3@43.9,-111.805 45.304,-111.805 45.749,-112.25 Q14.3@46,-112.25
NetQ15_1: Q15.1 R197.2 R349.2 | length 3.2
  Top Layer w0.254: Q15.1@48.45,-144.2 50.2,-144.2 R349.2@50.25,-144.25 ; R197.2@50.25,-145.5 R349.2@50.25,-144.25 ; R349.2@50.25,-144.1 R349.2@50.25,-144.25
NetQ15_3: Q15.3 U15.3 | length 2.3
  Top Layer w0.254: U15.3@43.75,-143.23 45.98,-143.23 Q15.3@46,-143.25
NetR9_1: R9.1 R53.1 R55.2 R103.2 R314.2 | length 5.9
  Top Layer w0.381: R314.2@20.25,-92 20.35,-91.9 R103.2@21.5,-91.9 ; R103.2@21.291,-92.16 21.5,-91.95 R103.2@21.5,-91.9 ; R9.1@23,-89.1 R55.2@21.5,-89.1 R103.2@21.5,-91.9
NetR9_2: R9.2 U4.10 | length 2.6
  Top Layer w0.381: R9.2@23,-87.4 23.07,-87.33 25.456,-87.33 U4.10@25.525,-87.261
NetR10_2: R10.2 U16.138 | length 2.5
  Top Layer w0.254: U16.138@89.551,-95.987 v1@89.551,-94.245
  Bottom Layer w0.254: v1(89.5,-94) 89.5,-93.35 R10.2@89.6,-93.25
NetR11_1: R11.1 U16.137 | length 18.4
  Top Layer w0.254: U16.137@89.051,-95.987 89.051,-99.765 90.75,-101.465 R11.1@90.75,-113.65
NetR12_1: R12.1 U16.136 | length 18
  Top Layer w0.254: U16.136@88.551,-95.987 88.551,-100.301 89.25,-101 R12.1@89.25,-113.65
NetR13_2: R13.2 U3.12 | length 15.8
  Top Layer w0.254: U3.12@31.572,-74.511 31.572,-76.572 32.5,-77.5 36,-77.5 37.75,-75.75 37.75,-71.25 38.5,-70.5 R13.2@39.4,-70.5
NetR14_2: R14.2 U3.11 | length 14.6
  Top Layer w0.254: U3.11@32.842,-74.511 32.842,-76.092 33.5,-76.75 35.5,-76.75 37,-75.25 37,-70 37.75,-69.25 R14.2@39.4,-69.25
NetR16_2: R16.2 U41.1 | length 2.3
  Top Layer w0.508: R16.2@108.292,-51.689 U41.1@110.55,-51.689
NetR19_2: R19.2 U16.44 | length 105.9
  Top Layer w0.254: R19.2@26.35,-27.5 29.25,-27.5 34.75,-33 v1(65,-33) ; v1(89,-33) 89.034,-33.034 89.034,-73.97 U16.44@89.051,-73.987
  S3 w0.254: v1(65,-33) v1(89,-33)
NetR20_2: R20.2 U16.132 | length 25.2
  Top Layer w0.254: R20.2@79.25,-118.15 79.25,-111 85.75,-104.5 85.75,-99.25 86.551,-98.449 U16.132@86.551,-95.987
NetR21_2: R21.2 U16.48 | length 2.8
  Top Layer w0.254: v1(87,-75.75) 87,-75.681 87.051,-75.631 U16.48@87.051,-73.987
  Bottom Layer w0.254: v1(87,-75.75) 87,-74.9 R21.2@87.15,-74.75
NetR22_2: R22.2 U11.1 | length 2.6
  Top Layer w0.381: R22.2@38.871,-92.241 38.871,-89.602 U11.1@38.875,-89.598
NetR23_2: R23.2 U16.45 | length 104.2
  Top Layer w0.254: R23.2@26.35,-29.25 29.25,-29.25 33.75,-33.75 65.717,-33.75 v1(65.75,-33.717) ; v1(88.25,-33.75) 88.25,-68 88.551,-68.301 U16.45@88.551,-73.987
  S3 w0.254: v1(65.75,-33.717) 65.767,-33.733 88.233,-33.733 v1(88.25,-33.75)
NetR24_1: R24.1 U16.98 | length 80.9
  Top Layer w0.254: R24.1@26.85,-121.5 v1(33.5,-121.5) ; v2(55,-88) 58.75,-88 59.487,-88.737 U16.98@72.801,-88.737
  S3 w0.254: v1(33.5,-121.5) 35.5,-121.5 37,-123 52,-123 52.75,-122.25 52.75,-89 53.75,-88 v2(55,-88)
NetR25_2: R25.2 U16.80 | length 86.9
  Top Layer w0.254: R25.2@26.35,-43 29.25,-43 32.5,-39.75 66.25,-39.75 66.75,-40.25 66.75,-78.75 67.737,-79.737 U16.80@72.801,-79.737
NetR26_2: R26.2 U16.129 | length 25.1
  Top Layer w0.254: R26.2@78,-118.15 78,-111.25 85.051,-104.199 U16.129@85.051,-95.987
NetR27_2: R27.2 U16.128 | length 25.5
  Top Layer w0.254: R27.2@76.75,-118.25 76.75,-112.25 76.75,-111.5 84.551,-103.699 U16.128@84.551,-95.987
NetR29_1: R29.1 U16.67 | length 16.3
  Top Layer w0.254: R29.1@76,-58.35 76,-68.25 77.551,-69.801 U16.67@77.551,-73.987
NetR30_1: R30.1 U16.66 | length 16
  Top Layer w0.254: R30.1@77.25,-58.35 77.25,-68 78.051,-68.801 U16.66@78.051,-73.987
NetR31_2: R31.2 U39.1 | length 2.1
  Top Layer w0.508: v1(113.284,-145.161) 113.284,-146.425 U39.1@113.295,-146.436
  Bottom Layer w0.254: v1(113.284,-145.161) R31.2@113.284,-144.36
NetR32_1: R32.1 U16.65 | length 15.7
  Top Layer w0.254: R32.1@78.5,-58.35 78.551,-58.401 U16.65@78.551,-73.987
NetR35_1: R35.1 U16.64 | length 15.9
  Top Layer w0.254: U16.64@79.051,-73.987 79.051,-68.699 79.75,-68 R35.1@79.75,-58.35
NetR36_2: R36.2 U5.1 | length 4.8
  Top Layer w0.254: U5.1@44.734,-47.899 44.734,-49.234 45.24,-49.74 48.022,-49.74 R36.2@48.032,-49.75
NetR37_1: R37.1 U29.3 | length 2.5
  Top Layer w0.254: R37.1@124.079,-130.136 124.079,-130.143 124.352,-130.416 U29.3@126.426,-130.416
NetR37_2: R37.2 U40.1 | length 2.2
  Top Layer w0.254: U40.1@122.174,-128.702 122.174,-128.609 122.347,-128.436 R37.2@124.206,-128.436
NetR41_2: R41.2 U5.4 | length 4.8
  Top Layer w0.254: U5.4@44.734,-44.089 44.734,-42.766 45.25,-42.25 R41.2@48.032,-42.25
NetR42_2: R42.2 U16.96 | length 82
  Top Layer w0.254: R42.2@26.85,-117.5 v1(33.5,-117.5) ; v2(55,-86.5) 59.25,-86.5 60.487,-87.737 U16.96@72.801,-87.737
  S3 w0.254: v1(33.5,-117.5) 33.549,-117.549 34.549,-117.549 38.75,-121.75 50.5,-121.75 51.25,-121 51.25,-88.25 53,-86.5 v2(55,-86.5)
NetR43_2: R43.2 U16.81 | length 85.7
  Top Layer w0.254: R43.2@26.35,-46 28.5,-46 33.25,-41.25 64.25,-41.25 65.75,-42.75 65.75,-78.75 67.237,-80.237 U16.81@72.801,-80.237
NetR45_1: R45.1 X3.3 | length 5
  Top Layer w0.254: R45.1@103.85,-82.75 103.864,-82.736 X3.3@108.803,-82.736 X3.3@108.789,-82.75
NetR47_2: R47.2 U16.127 | length 25.8
  Top Layer w0.254: R47.2@75.5,-118.202 R47.2@75.5,-118.15 75.5,-111.75 84.051,-103.199 U16.127@84.051,-95.987
NetR48_1: R48.1 U17.42 | length 4
  Top Layer w0.254: R48.1@67.184,-185.396 67.184,-185.897 68.704,-187.417 U17.42@68.704,-188.809
NetR49_1: R49.1 U3.14 | length 9.6
  Top Layer w0.254: 27.407,-76.302 R49.1@24.345,-76.302 28.55,-76.302 29.032,-75.819 U3.14@29.032,-74.511 U3.14@29.032,-74.13
NetR50_1: R50.1 R57.1 U8.1 | length 19.8
  Top Layer w0.254: R57.1@21.35,-136.5 23.75,-136.5 25.5,-138.25 28.8,-138.25 30.268,-136.782 30.268,-136.582 32.168,-136.582 33,-135.75 33,-133.5 33.27,-133.23 U8.1@36.95,-133.23
NetR51_2: R51.2 U6.3 | length 6.5
  Top Layer w0.254: U6.3@107.59,-73.49 109.51,-73.49 110.25,-72.75 R51.2@110.25,-69.2
NetR52_1: R52.1 U3.13 | length 8.9
  Top Layer w0.254: R52.1@24.345,-77.724 29.21,-77.724 30.302,-76.632 U3.13@30.302,-74.511 U3.13@30.302,-74.13
NetR56_2: R56.2 U16.104 | length 94.5
  Top Layer w0.254: U16.104@72.801,-91.737 75.263,-91.737 v1(75.75,-91.25) ; v1(98.25,-60.75) 98.25,-48 100,-46.25 104.5,-46.25 106.25,-44.5 106.25,-38.5 108,-36.75 R56.2@119,-36.75
  S3 w0.254: v1(75.75,-91.25) 75.75,-89.75 78.5,-87 88.5,-87 89.5,-86 89.5,-74.13 90.63,-73 95.75,-73 99.5,-69.25 99.5,-62.75 98.25,-61.5 v1(98.25,-60.75)
NetR59_2: R59.2 U16.126 | length 26
  Top Layer w0.254: R59.2@74.25,-118.172 R59.2@74.25,-118.15 74.25,-112 83.551,-102.699 U16.126@83.551,-95.987
NetR60_1: R60.1 U17.41 | length 3.9
  Top Layer w0.254: R60.1@68.454,-185.269 68.454,-186.126 69.204,-186.876 U17.41@69.204,-188.809
NetR74_2: R74.2 RJ1.4 RJ1.5 | length 8.7
  Bottom Layer w0.508: RJ1.5@12.55,8.047 13.82,9.317 RJ1.4@15.09,9.317 16.433,9.317 18.431,7.319 R74.2@19.928,7.319
NetR76_2: R76.2 RJ1.7 RJ1.8 | length 8.7
  Bottom Layer w0.254: R76.2@19.75,5.329 R76.2@19.927,5.506
  Bottom Layer w0.508: RJ1.7@12.55,5.507 13.82,4.237 RJ1.8@15.09,4.237 16.359,5.506 19.927,5.506 R76.2@19.928,5.506
NetR77_1: R77.1 U9.45 | length 5.7
  Top Layer w0.254: R77.1@45.612,10.753 45.612,9.266 46.196,8.682 47.974,8.682 48.342,8.314 U9.45@48.342,7.213
NetR80_2: R80.2 U9.10 | length 3.1
  Top Layer w0.254: R80.2@41.95,0.963 U9.10@45.092,0.963
NetR81_1: R81.1 U9.44 | length 5.1
  Top Layer w0.254: R81.1@46.786,10.753 46.786,9.743 47.263,9.266 48.431,9.266 48.842,8.855 U9.44@48.842,7.213
NetR82_1: R82.1 U9.43 | length 4.5
  Top Layer w0.254: R82.1@47.961,10.753 47.961,10.066 48.202,9.825 48.787,9.825 49.342,9.27 U9.43@49.342,7.213
NetR83_2: R83.2 U9.23 | length 3.1
  Top Layer w0.254: R83.2@51.842,-4.895 U9.23@51.842,-1.787
NetR84_2: R84.2 U9.38 | length 4.8
  Top Layer w0.254: U9.38@51.842,7.213 51.842,8.664 52.597,9.419 53.384,9.419 53.835,9.87 R84.2@53.835,10.753
NetR85_2: R85.2 U9.39 | length 4.1
  Top Layer w0.254: U9.39@51.342,7.213 51.342,9.053 52.66,10.371 R85.2@52.66,10.753
NetR86_2: R86.2 U9.40 | length 3.8
  Top Layer w0.254: U9.40@50.842,7.213 50.842,9.518 51.485,10.162 R86.2@51.485,10.753
NetR87_2: R87.2 U9.41 | length 3.6
  Top Layer w0.254: R87.2@50.311,10.753 50.342,10.722 U9.41@50.342,7.213
NetR88_2: R88.2 U9.42 | length 3.8
  Top Layer w0.254: R88.2@49.136,10.753 49.136,10.212 49.842,9.506 U9.42@49.842,7.213
NetR89_2: R89.2 U6.7 | length 5.2
  Top Layer w0.254: R89.2@112.75,-69.2 112.75,-71.75 113.22,-72.22 U6.7@115.19,-72.22
NetR90_2: R90.2 U16.85 | length 112.9
  Top Layer w0.254: v1(64.25,-70.25) 64.25,-79.5 66.987,-82.237 U16.85@72.801,-82.237 ; v1(96.75,-60.75) 96.75,-47 99,-44.75 103.25,-44.75 104.75,-43.25 104.75,-37.75 106,-36.5 106,-30 107.25,-28.75 R90.2@119.65,-28.75
  S3 w0.254: v1(64.25,-70.25) 96.25,-70.25 98,-68.5 98,-63.25 96.75,-62 v1(96.75,-60.75)
NetR91_2: R91.2 U6.2 | length 11.2
  Top Layer w0.254: U6.2@107.59,-72.22 107.605,-72.235 109.485,-72.235 v1(109.5,-72.25) ; v1(117.25,-73.75) R91.2@118.15,-73.75
  S3 w0.254: v1(109.5,-72.25) 111,-73.75 v1(117.25,-73.75)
